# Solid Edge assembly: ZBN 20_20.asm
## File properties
Title: Zylinder
Author: bmolnar
Template: iso metric assembly.asm
Last saved by: bmolnar
Revision: 11
Application: Solid Edge
Username: bmolnar
Dokumentum tartalom típus: 1
Document Number: ZBN 20/20
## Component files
Kit_1.par
Kit_2.par
Profilrohr.par
Kolbenstange.par
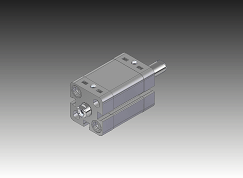
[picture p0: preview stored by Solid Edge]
